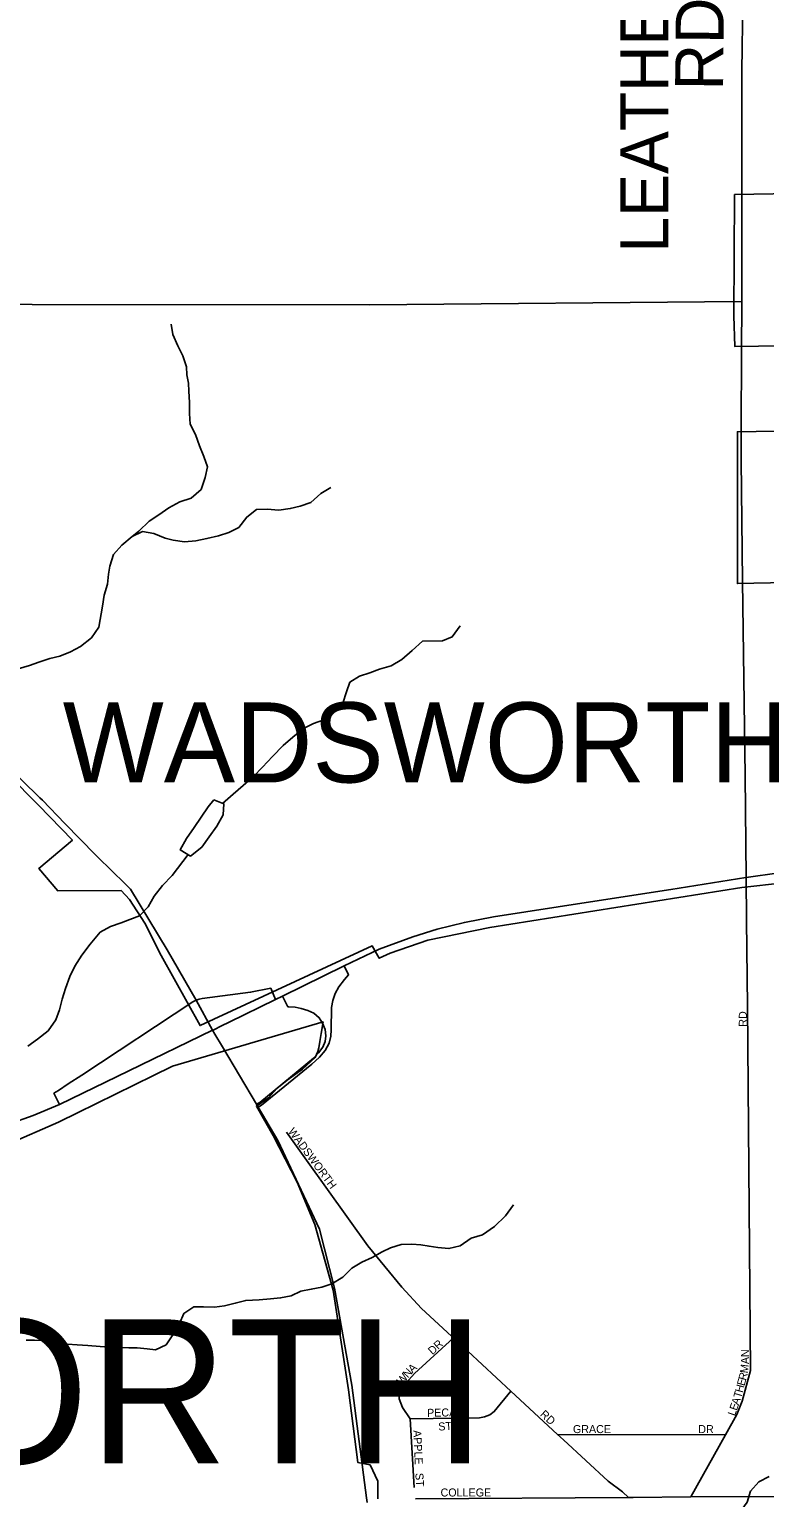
# Model space of a CAD drawing. Extents: x 1985906 to 2277390, y 930619 to 1324581.
# Drawn here: x 2171119 to 2175713, y 1102890 to 1112061 of the extents above; entities that cross this region are included whole.
import ezdxf

# ---------------------------------------------------------------- set-up
doc = ezdxf.new("R2010")
doc.units = 0
for name, color, linetype in [('GM_X_City_Street', 7, 'Continuous'), ('GM_X_City_Street_Text', 7, 'Continuous'), ('GM_X_Corporation', 7, 'Continuous'), ('GM_X_Corporation_Text', 7, 'Continuous'), ('GM_X_County_Road', 7, 'Continuous'), ('GM_X_County_Road_Text', 7, 'Continuous'), ('GM_X_Interchange_Ramps', 7, 'Continuous'), ('GM_X_Interstate_Route', 7, 'Continuous'), ('GM_X_Minor_Lake', 7, 'Continuous'), ('GM_X_Minor_River', 7, 'Continuous'), ('GM_X_State_Route', 7, 'Continuous'), ('GM_X_Township_Road', 7, 'Continuous'), ('GM_X_Township_Text', 7, 'Continuous')]:
    doc.layers.add(name, color=color, linetype=linetype)

msp = doc.modelspace()

# ---------------------------------------------------------------- linework, layer by layer
at = {"layer": 'GM_X_City_Street'}
for points in [[(2175606.2, 1105960.6), (2175601.1, 1106495.3)], [(2175251.2, 1102894.1), (2175469, 1103283), (2175539.5, 1103408.8), (2175573.3, 1103493.1), (2175624.9, 1103684.4), (2175608.6, 1105711.5), (2175606.2, 1105960.6)], [(2172851.1, 1104997), (2172725.2, 1105173.2)], [(2174862.8, 1102891.7), (2174824.7, 1102925.8), (2174736.6, 1102993.6), (2174456, 1103251), (2174418.8, 1103285.4), (2174126.9, 1103556), (2173768.7, 1103887.9), (2173756.4, 1103899.3), (2173570, 1104070.9), (2173445.7, 1104204.6), (2173233.1, 1104462.2), (2172851.1, 1104997)], [(2173498.1, 1103382.1), (2173449.9, 1103454), (2173429.8, 1103508), (2173431.7, 1103544), (2173451.6, 1103584.1), (2173525.3, 1103664.4), (2173768.7, 1103887.9)], [(2173498.1, 1103382.1), (2173931.8, 1103389.4), (2173963.8, 1103395.5), (2173995.8, 1103407.7), (2174023.7, 1103427.8), (2174126.9, 1103556)], [(2173523.4, 1102953.8), (2173498.1, 1103382.1)], [(2174418.8, 1103285.4), (2175469, 1103283)], [(2173532.7, 1102883.6), (2174862.8, 1102891.7), (2174886.6, 1102891.9)], [(2174886.6, 1102891.9), (2174892.3, 1102891.9), (2175251.2, 1102894.1), (2175898.9, 1102898.1)]]:
    msp.add_lwpolyline(points, dxfattribs=at)
at = {"layer": 'GM_X_Corporation'}
for points in [[(2178191.3, 1110117.3), (2175526.6, 1110080.5), (2175521.8, 1110272.2), (2175525.4, 1111029.3), (2176370, 1111043.8)], [(2177291.1, 1108635.5), (2175543.2, 1108599.3), (2175543.2, 1109547), (2177290.6, 1109577.5)], [(2170608.8, 1107785.7), (2171176.3, 1107215.7), (2171387.8, 1106997.4), (2171178.6, 1106820.5), (2171296.7, 1106680.7), (2171691.9, 1106682.1), (2171743.7, 1106625.7), (2171841, 1106478.9), (2171941.9, 1106276.1), (2172186.2, 1105838.7), (2173260.8, 1106337.1), (2173305.2, 1106258.8), (2173372.9, 1106290.1), (2173608.1, 1106373), (2173996.6, 1106452.1), (2175571.6, 1106701.6), (2175831.3, 1106729.7)], [(2173297, 1102882.1), (2173296.2, 1102992.2), (2173247.9, 1103094.6), (2173170.9, 1103110.1), (2173113.4, 1103562.6), (2173016.3, 1104185.7), (2172902.8, 1104596.8), (2172792.1, 1104860.5), (2172642.2, 1105152.5), (2172537.3, 1105335.8), (2172613.4, 1105387.9), (2172664.8, 1105444.5), (2172730.2, 1105497.3), (2172825.4, 1105566.5), (2172876.8, 1105615.1), (2172904.6, 1105639.4), (2172922.2, 1105675.7), (2172927.9, 1105699.7), (2172933.5, 1105739.8), (2172943, 1105788), (2172954.8, 1105861), (2172012.4, 1105585), (2171300.4, 1105236.1), (2170987.2, 1105097.6)]]:
    msp.add_lwpolyline(points, dxfattribs=at)
at = {"layer": 'GM_X_County_Road'}
for points in [[(2175570.1, 1110987.6), (2175570.1, 1111799.8), (2175576.5, 1112241.8)], [(2175569, 1110043), (2175570.1, 1110360.4), (2175570.1, 1110850.8), (2175570.1, 1110987.6)], [(2175567.3, 1109566.8), (2175569, 1110043)], [(2175575.8, 1108614.4), (2175566.6, 1109369.1), (2175567.3, 1109566.8)], [(2175590.7, 1107397.6), (2175575.8, 1108614.4)], [(2175601.1, 1106495.3), (2175598.5, 1106762.7), (2175590.7, 1107397.6)]]:
    msp.add_lwpolyline(points, dxfattribs=at)
at = {"layer": 'GM_X_Interchange_Ramps'}
for points in [[(2172549.2, 1105328.7), (2172570, 1105340.6), (2172883.8, 1105597.9), (2172932.4, 1105640.9), (2172967.1, 1105682.2), (2172992.5, 1105729), (2173001.9, 1105771.4), (2173003.9, 1105812), (2173007.7, 1105952.3), (2173015.1, 1105995.4), (2173029.2, 1106038.4), (2173053.2, 1106081.3), (2173087.3, 1106127.2), (2173112.2, 1106155.2), (2173086.1, 1106211.5)], [(2172161.2, 1105997.1), (2172141, 1105986.9), (2171447.7, 1105529.4), (2171361.6, 1105475), (2171301, 1105432.9), (2171272.4, 1105416.3), (2171307.3, 1105346.1)], [(2172656.8, 1106001.5), (2172627.6, 1106071.8), (2172500.9, 1106046.7), (2172198.4, 1106007.2), (2172179.1, 1106002.9), (2172161.2, 1105997.1)], [(2172701.6, 1106023.2), (2172734.7, 1105955.9), (2172740.3, 1105956.4), (2172779.6, 1105953.7), (2172818, 1105945.7), (2172858.4, 1105933.6), (2172896.6, 1105915.7), (2172930.1, 1105887.2), (2172950.8, 1105854.2), (2172966.7, 1105814), (2172972, 1105775.3), (2172968.1, 1105738.8), (2172953.5, 1105703.8), (2172926.3, 1105667.7), (2172893.8, 1105635.6), (2172558.3, 1105358.1), (2172538.5, 1105346.8)]]:
    msp.add_lwpolyline(points, dxfattribs=at)
at = {"layer": 'GM_X_Interstate_Route'}
for points in [[(2175596.9, 1106762.4), (2175598.5, 1106762.7), (2175803.2, 1106792.5), (2176117.5, 1106844.6), (2176329.3, 1106885.4), (2176544.6, 1106941.8), (2176687.8, 1106992.2), (2176858.8, 1107067.7), (2177025.5, 1107162.3), (2177139.2, 1107235.2), (2177264.2, 1107330.7), (2177382.4, 1107433.8), (2177576.7, 1107639.8), (2177785.9, 1107910.6), (2177950.9, 1108131.8)], [(2172656.8, 1106001.5), (2172701.6, 1106023.2), (2173086.1, 1106211.5), (2173304.2, 1106314.8), (2173515.2, 1106392.9), (2173668, 1106440.6), (2173837.2, 1106483.2), (2174019.5, 1106517.9), (2174624.6, 1106611.6), (2175128, 1106688), (2175596.9, 1106762.4)], [(2172368.1, 1105859.9), (2172656.8, 1106001.5)], [(2171741.4, 1105556.1), (2172263.9, 1105808.8), (2172271.9, 1105812.7)], [(2172271.9, 1105812.7), (2172320, 1105836.3)], [(2172320, 1105836.3), (2172368.1, 1105859.9)], [(2169340.5, 1105095.5), (2169627.6, 1105092.7), (2170126.8, 1105089.2), (2170343.8, 1105098.7), (2170579, 1105129.1), (2170786.5, 1105168.2), (2170990.8, 1105223.5), (2171143.3, 1105277.6), (2171307.3, 1105346.1), (2171741.4, 1105556.1)]]:
    msp.add_lwpolyline(points, dxfattribs=at)
at = {"layer": 'GM_X_Minor_Lake'}
for points in [[(2172272.5, 1107247.7), (2172237.2, 1107205), (2172192.4, 1107140.1), (2172149.5, 1107075.1), (2172100.7, 1107006.1), (2172062, 1106935.3), (2172126.1, 1106896.9)], [(2172272.5, 1107247.7), (2172237.2, 1107205), (2172192.4, 1107140.1), (2172149.5, 1107075.1), (2172100.7, 1107006.1), (2172062, 1106935.3), (2172126.1, 1106896.9)], [(2172126.1, 1106896.9), (2172195.8, 1106953.8), (2172242.7, 1107016.8), (2172289.5, 1107083.8), (2172330.3, 1107154.6), (2172335, 1107222.8), (2172272.5, 1107247.7)], [(2172126.1, 1106896.8), (2172195.8, 1106953.8), (2172242.7, 1107016.8), (2172289.5, 1107083.8), (2172330.3, 1107154.6), (2172335, 1107222.8), (2172272.5, 1107247.7)]]:
    msp.add_lwpolyline(points, dxfattribs=at)
at = {"layer": 'GM_X_Minor_River'}
for points in [[(2171761.1, 1108893.1), (2171802.6, 1108925.9), (2171867.5, 1108989.2), (2171928.8, 1109028.4), (2171990.1, 1109071.7), (2172059.5, 1109109), (2172129.2, 1109132.4), (2172192.2, 1109187.6), (2172216.9, 1109262.2), (2172231.7, 1109328.6), (2172208.4, 1109392.3), (2172181.1, 1109459.9), (2172157.8, 1109529.6), (2172124.6, 1109595.1), (2172119.3, 1109661.1), (2172120, 1109731.2), (2172114.7, 1109801.2), (2172113.8, 1109851.3), (2172102.8, 1109903.2), (2172099.8, 1109953.2), (2172078.6, 1110020.9), (2172047.3, 1110084.5), (2172016, 1110154), (2172004.7, 1110219.9)], [(2171761.1, 1108893.1), (2171826.6, 1108924.4), (2171897, 1108911.7), (2171967.6, 1108882.9), (2172017.9, 1108869.8), (2172088.2, 1108859.1), (2172158.2, 1108866.4), (2172228, 1108879.8), (2172299.8, 1108897.1), (2172365.5, 1108918.4), (2172427, 1108949.6), (2172477.8, 1109014.6), (2172539, 1109061.9), (2172605.1, 1109063.1), (2172677.3, 1109058.4), (2172749.2, 1109067.8), (2172811, 1109083), (2172876.7, 1109106.2), (2172939.7, 1109161.5), (2173003.1, 1109198.8)], [(2171049.6, 1108066.4), (2171119.3, 1108087.7), (2171179, 1108108.9), (2171246.7, 1108130.2), (2171308.4, 1108145.3), (2171376, 1108172.7), (2171437.5, 1108205.9), (2171506.6, 1108261.2), (2171553.4, 1108326.2), (2171575, 1108458.9), (2171585.7, 1108527.2), (2171606.5, 1108595.7), (2171613.3, 1108657.9), (2171622.4, 1108708.2), (2171645.1, 1108780.7), (2171696, 1108839.8), (2171761.1, 1108893.1)], [(2172326.2, 1107226.4), (2172392, 1107284), (2172455.1, 1107337.3), (2172520.1, 1107394.6), (2172575.1, 1107451.7), (2172637.9, 1107519), (2172704.7, 1107588.4), (2172765.8, 1107639.6), (2172830.9, 1107694.9), (2172894.4, 1107726.1), (2172958.1, 1107747.4), (2173019.3, 1107794.6), (2173078.3, 1107851.8), (2173101, 1107922.3), (2173121.9, 1107982.8), (2173181.3, 1108020), (2173247, 1108041.3), (2173306.7, 1108064.4), (2173380.4, 1108085.8), (2173445.7, 1108125.1), (2173510.8, 1108180.4), (2173575.8, 1108239.7), (2173699.9, 1108242.1), (2173761.5, 1108267.2), (2173810.3, 1108334.3)], [(2171109.5, 1105709.3), (2171170.8, 1105752.6), (2171235.9, 1105805.9), (2171284.7, 1105874.9), (2171307.6, 1105937.4), (2171324.3, 1106003.9), (2171345.1, 1106070.4), (2171371.8, 1106145), (2171402.6, 1106209.7), (2171447.4, 1106278.6), (2171498.2, 1106347.7), (2171560.9, 1106421), (2171626.3, 1106456.3), (2171692, 1106479.6), (2171747.7, 1106500.6), (2171807.3, 1106523.8), (2171860.3, 1106580.9), (2171899.1, 1106647.7), (2171950, 1106712.8), (2172010.9, 1106776), (2172110.5, 1106906.2)], [(2171099.7, 1103873.9), (2171151.8, 1103872.9), (2171217.9, 1103872.1), (2171284.2, 1103861.3), (2171356.5, 1103848.6), (2171416.7, 1103843.8), (2171484.8, 1103841), (2171561, 1103834.4), (2171615.2, 1103829.4), (2171683.3, 1103828.7), (2171741.4, 1103825.8), (2171793.5, 1103826.7), (2171855.7, 1103819.9), (2171907.9, 1103812.8), (2171973.4, 1103844.1), (2172020.2, 1103913.1), (2172057, 1103977.9), (2172083.9, 1104040.5), (2172147.2, 1104081.8), (2172207.3, 1104080.9), (2172275.4, 1104080.1), (2172337.4, 1104087.3), (2172405.1, 1104104.6), (2172470.9, 1104121.9), (2172555, 1104125.4), (2172624.9, 1104132.8), (2172688.9, 1104138), (2172754.7, 1104151.2), (2172814.3, 1104180.4), (2172880.2, 1104191.6), (2172946, 1104204.9), (2173009.7, 1104226.1), (2173077, 1104267.4), (2173134.1, 1104322.6), (2173197.4, 1104361.8), (2173261, 1104389.1), (2173324.4, 1104426.3), (2173376, 1104451.3), (2173441.7, 1104470.6), (2173509.8, 1104473.8), (2173565.9, 1104468.9), (2173616.2, 1104459.8), (2173670.4, 1104452.8), (2173740.6, 1104446.1), (2173810.4, 1104463.4), (2173879.6, 1104510.8), (2173951.3, 1104532.1), (2174024.4, 1104583.6), (2174093.2, 1104651), (2174144.1, 1104718.1)], [(2175742.5, 1103023.1), (2175676.7, 1102988.2), (2175625.2, 1102931.3), (2175603.9, 1102860.8), (2175521.4, 1102746.6)]]:
    msp.add_lwpolyline(points, dxfattribs=at)
at = {"layer": 'GM_X_State_Route'}
for points in [[(2171200.4, 1107245.4), (2171185.2, 1107261.1), (2170624.8, 1107809.3), (2170413.5, 1108029.8)], [(2171533.2, 1106904.7), (2171340.4, 1107101.6), (2171200.4, 1107245.4)], [(2172263.9, 1105808.8), (2172161.2, 1105997.1), (2171979.5, 1106310.8), (2171751, 1106690.3), (2171717.5, 1106723.2), (2171547.3, 1106890.3), (2171533.2, 1106904.7)], [(2172324.9, 1105706.1), (2172278.3, 1105784.6), (2172263.9, 1105808.8)], [(2173229.8, 1102859.7), (2173226.4, 1102888.4), (2173133.7, 1103592.4), (2173025.9, 1104197.8), (2172931.1, 1104566.6), (2172672.4, 1105119.7), (2172549.2, 1105328.7), (2172538.5, 1105346.8), (2172324.9, 1105706.1)]]:
    msp.add_lwpolyline(points, dxfattribs=at)
at = {"layer": 'GM_X_Township_Road'}
msp.add_lwpolyline([(2168737.9, 1110348.5), (2168737.9, 1110348.5), (2169421.2, 1110353.4), (2170625.6, 1110346), (2171135.7, 1110342.8), (2173245.3, 1110339.3), (2175570.1, 1110360.4)], dxfattribs=at)

# ---------------------------------------------------------------- texts
at = {"layer": 'GM_X_City_Street_Text'}
for s, rotation, p in [('RD', 90, (2175602, 1105831.4)), ('WADSWORTH', 306.62254, (2172732.5, 1105176.8)), ('DR', 42.8801, (2173638, 1103779.1)), ('N', 90, (2175615.2, 1103767.9)), ('N', 47.61309, (2173484.1, 1103634.2)), ('A', 43.77915, (2173513.1, 1103666.1)), ('M', 82.92912, (2175608.4, 1103664.6)), ('A', 90.19539, (2175615.3, 1103723.9)), ('W', 49.35494, (2173447.1, 1103591.1)), ('E', 74.56098, (2175587, 1103584.7)), ('R', 74.53828, (2175596.3, 1103618.6)), ('D', 81.48975, (2173423.7, 1103515)), ('A', 63.05376, (2173428.9, 1103554.5)), ('T', 74.05411, (2175565.4, 1103508)), ('H', 74.55263, (2175575.2, 1103542.3)), ('PECAN', 1.24464, (2173604.6, 1103394.4)), ('RD', 317.1199, (2174306.4, 1103405.1)), ('L', 70.87373, (2175527.7, 1103396.8)), ('E', 70.86487, (2175539.2, 1103430.1)), ('A', 71.77801, (2175551, 1103464.1)), ('ST', 3.57463, (2173675.6, 1103308.5)), ('GRACE', 0.00001, (2174515.6, 1103293.2)), ('DR', 0.00001, (2175298.8, 1103293.2)), ('APPLE', 272.72484, (2173517.4, 1103310.6)), ('ST', 273.57465, (2173530.6, 1103042.4)), ('COLLEGE', 0.00001, (2173688.4, 1102897.2))]:
    msp.add_text(s, height=50, rotation=rotation, dxfattribs=at).set_placement(p)
at = {"layer": 'GM_X_Corporation_Text'}
msp.add_text('WADSWORTH', height=500, rotation=0.00001, dxfattribs=at).set_placement((2171327.6, 1107357))
at = {"layer": 'GM_X_County_Road_Text'}
for s, rotation, p in [('LEATHERMAN', 89.99961, (2175111.4, 1110667.1)), ('RD', 89.51118, (2175453.7, 1111678.3))]:
    msp.add_text(s, height=300, rotation=rotation, dxfattribs=at).set_placement(p)
at = {"layer": 'GM_X_Township_Text'}
msp.add_text('WADSWORTH', height=900, rotation=0.00001, dxfattribs=at).set_placement((2165807.6, 1103103.5))

doc.saveas('drawing.dxf')
